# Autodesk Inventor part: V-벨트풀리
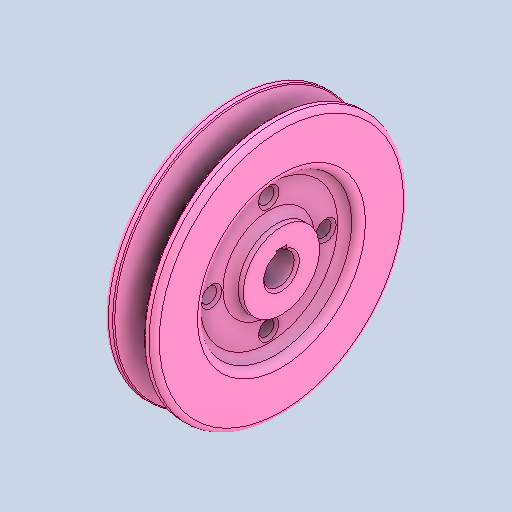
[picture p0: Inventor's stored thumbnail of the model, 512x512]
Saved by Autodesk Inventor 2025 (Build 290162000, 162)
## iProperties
Created: 2024-07
Part Number: V-벨트풀리
Material: 강철, 연강
Document SubType Name: Modeling
Designer: onair
Density: 7.86 g/cm^3
Appearance: 기본값
Author: jhkim
Sending System: Autodesk Inventor 2025
Preprocessor: ST-DEVELOPER v20
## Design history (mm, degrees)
feature "솔리드1"
node "솔리드2"
